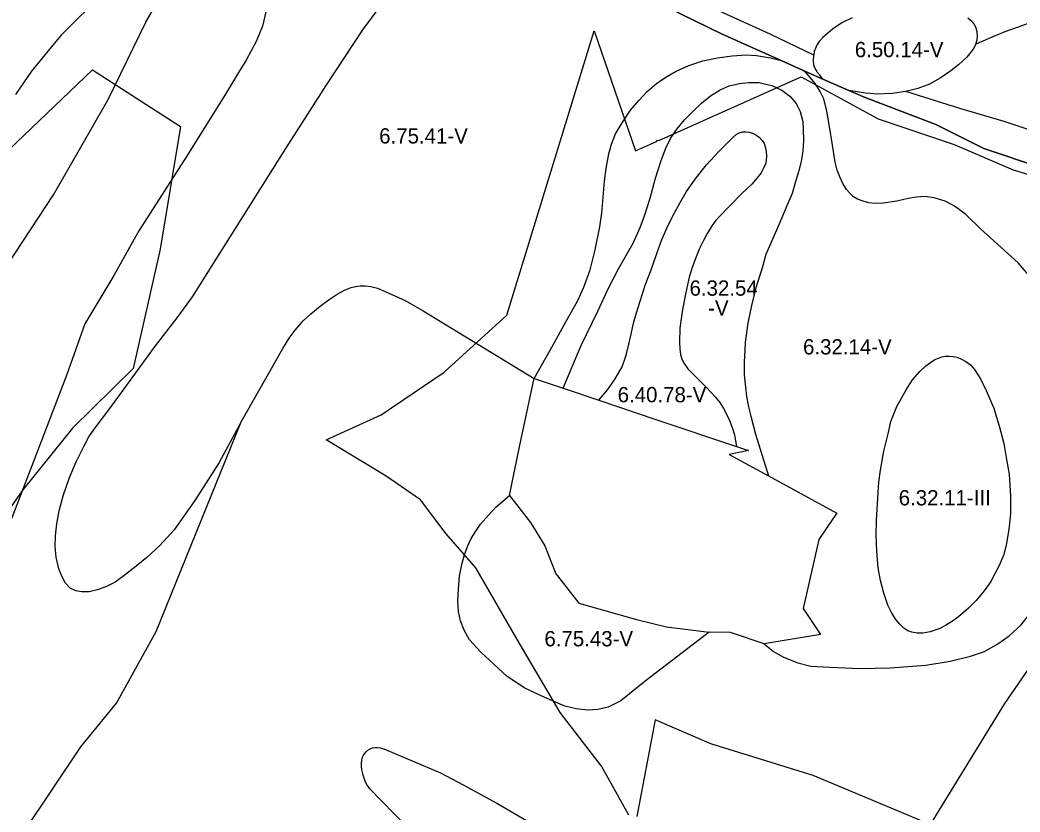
# Model space of a CAD drawing. Extents: x -555156 to -540209, y -1046851 to -1035695.
# Drawn here: x -543276 to -542621, y -1041348 to -1040830 of the extents above; entities that cross this region are included whole.
import ezdxf

# ---------------------------------------------------------------- set-up
doc = ezdxf.new("R2010")
doc.units = 0
for name, color, linetype in [('Vrstva 27', 7, 'Continuous'), ('Vrstva 28', 7, 'Continuous'), ('Vrstva 29', 7, 'Continuous')]:
    doc.layers.add(name, color=color, linetype=linetype)

msp = doc.modelspace()

# ---------------------------------------------------------------- linework, layer by layer
at = {"layer": 'Vrstva 28'}
for points in [[(-542750.36, -1040868.71), (-542763.73, -1040862.75), (-542777.64, -1040856.56), (-542816.73, -1040839.15), (-542851.59, -1040821.98), (-542893.18, -1040804.96), (-542959.22, -1040781.23), (-542988.31, -1040771.92)], [(-543114.91, -1040780.64), (-543113, -1040792.52), (-543112.57, -1040803.33), (-543112.79, -1040813.08), (-543114.48, -1040823.69), (-543117.02, -1040834.08), (-543121.05, -1040844.04), (-543127.62, -1040856.34), (-543132.71, -1040864.4), (-543140.55, -1040877.5), (-543166.14, -1040918.69), (-543197.89, -1040967.9), (-543214.21, -1040997.22), (-543233.03, -1041028.81), (-543244.9, -1041062.1), (-543267.79, -1041121.9), (-543281.99, -1041158.59)], [(-542959.22, -1040781.23), (-542909.59, -1040799.06), (-542893.18, -1040804.96), (-542851.59, -1040821.98), (-542816.73, -1040839.15), (-542777.68, -1040856.54)], [(-543293.87, -1041005.52), (-543253.63, -1040944.47), (-543217.93, -1040882.13), (-543193.27, -1040831.47), (-543168.15, -1040787.72)], [(-543168.15, -1040787.72), (-543177.6, -1040791.96), (-543189.11, -1040796.93), (-543197, -1040800.47), (-543210.35, -1040807.47), (-543220.95, -1040814.25), (-543229.21, -1040820.83), (-543239.6, -1040831.01), (-543248.92, -1040840.12), (-543257.19, -1040850.09), (-543268, -1040863.45), (-543278.38, -1040878.72)], [(-543130.8, -1041093.03), (-543145.27, -1041119.62), (-543161.13, -1041144.58), (-543174.7, -1041163.61), (-543184.14, -1041173.91), (-543192.53, -1041181.84), (-543198.49, -1041186.61), (-543207.55, -1041193.82), (-543213.23, -1041197.83), (-543219.04, -1041200.88), (-543224.92, -1041202.96), (-543230.32, -1041204.2), (-543235.1, -1041204.27), (-543239.11, -1041203.51), (-543242.71, -1041201.78), (-543245.74, -1041198.58), (-543248.28, -1041193.97), (-543250.22, -1041189.12), (-543251.79, -1041181.61), (-543252.52, -1041174.7), (-543252.28, -1041167.68), (-543251.55, -1041159.68), (-543249.97, -1041151.32), (-543247.35, -1041141.35), (-543243.11, -1041129.48), (-543238.75, -1041119.18), (-543233.66, -1041108.76), (-543230.51, -1041102.82), (-543227.12, -1041097.73), (-543216.74, -1041084.25), (-543207.31, -1041071.47), (-543187.6, -1041044.12), (-543172.13, -1041023.97), (-543162.8, -1041011.25), (-543101.67, -1040914.04), (-543075.39, -1040872.9), (-543051.23, -1040836.43), (-543033.64, -1040812.47)], [(-542756.44, -1040853.01), (-542785, -1040839.22), (-542848.26, -1040810.19), (-542852.98, -1040808.28)], [(-542731.25, -1040828.69), (-542737.56, -1040831.59), (-542741.32, -1040833.98), (-542744.05, -1040835.95), (-542747.21, -1040838.59), (-542750.37, -1040841.41), (-542752.76, -1040844.14), (-542754.19, -1040846.13), (-542755.12, -1040847.94), (-542756.1, -1040850.57), (-542756.44, -1040853.01)], [(-542650.35, -1040845.79), (-542649.58, -1040843.06), (-542649.33, -1040840.49), (-542649.58, -1040837.76), (-542650.27, -1040835.28), (-542651.29, -1040832.89), (-542653.08, -1040830.93), (-542655.56, -1040828.88)], [(-542615.09, -1040831.94), (-542622.74, -1040834.63), (-542630.36, -1040837.32), (-542637.68, -1040840.31), (-542650.35, -1040845.79)], [(-542650.35, -1040845.79), (-542652.15, -1040849.03), (-542656.18, -1040854.26), (-542661.7, -1040859.35), (-542666.63, -1040863.38), (-542673.8, -1040868.01), (-542680.67, -1040871.9), (-542688.29, -1040874.74), (-542696.06, -1040876.83)], [(-542939.35, -1041064.58), (-542926.79, -1041042.67), (-542918.53, -1041027.62), (-542910.9, -1041014.05), (-542906.87, -1041004.93), (-542902.63, -1040993.48), (-542899.45, -1040980.33), (-542896.27, -1040965.28), (-542895, -1040956.37), (-542894.15, -1040945.98), (-542893.31, -1040935.59), (-542892.25, -1040927.11), (-542890.37, -1040917.64), (-542888.67, -1040911.34), (-542886.01, -1040904.43), (-542881.77, -1040897.4), (-542876.32, -1040888.92), (-542870.87, -1040882.62), (-542865.3, -1040876.8), (-542859.25, -1040871.59), (-542853.07, -1040867.35), (-542846.41, -1040863.59), (-542838.05, -1040859.84), (-542828.85, -1040856.69), (-542819.4, -1040854.75), (-542809.83, -1040853.42), (-542800.51, -1040852.81), (-542793.73, -1040853.17)], [(-542793.73, -1040853.17), (-542784.64, -1040854.75), (-542777.68, -1040856.54)], [(-542777.68, -1040856.54), (-542763.73, -1040862.75)], [(-542752.24, -1040866.38), (-542754.15, -1040864.09), (-542754.66, -1040863.13), (-542755.46, -1040861.65), (-542756.29, -1040859.46), (-542756.63, -1040856.48), (-542756.44, -1040853.01)], [(-542605.19, -1041009.3), (-542622.63, -1040988.87), (-542647.58, -1040966.45), (-542656.91, -1040957.36), (-542664.29, -1040951.91), (-542670.35, -1040948.64), (-542677.62, -1040946.45), (-542683.43, -1040945.49), (-542689.12, -1040945.85), (-542694.7, -1040946.73), (-542702.1, -1040948.53), (-542710.89, -1040949.78), (-542715.73, -1040950.06), (-542720.3, -1040949.64), (-542724.11, -1040948.6), (-542727.84, -1040947.22), (-542730.34, -1040945.76), (-542732.83, -1040943.41), (-542734.9, -1040940.92), (-542737.33, -1040936.97), (-542739.33, -1040932.75), (-542740.99, -1040928.18), (-542742.33, -1040923.02), (-542744.14, -1040911.99), (-542746.2, -1040899.63), (-542747.9, -1040889.69), (-542749.76, -1040881.63), (-542752.12, -1040876.72), (-542755.51, -1040871.66), (-542758.55, -1040867.78), (-542761.46, -1040864.67), (-542763.73, -1040862.75)], [(-542763.73, -1040862.75), (-542750.36, -1040868.71)], [(-542920.34, -1041070.98), (-542908.65, -1041043.54), (-542897.63, -1041020.64), (-542891.06, -1041006.43), (-542884.06, -1040992.86), (-542874.53, -1040976.11), (-542869.86, -1040965.72), (-542867.09, -1040958.26), (-542863.49, -1040946.59), (-542859.89, -1040933.45), (-542856.29, -1040921.99), (-542853.11, -1040913.94), (-542850.14, -1040907.58), (-542845.99, -1040901.52), (-542840.91, -1040895.34), (-542835.58, -1040889.88), (-542829.76, -1040884.43), (-542823.95, -1040879.71), (-542817.53, -1040875.71), (-542811.72, -1040873.16), (-542804.94, -1040871.59), (-542798.88, -1040870.86), (-542792.34, -1040870.98)], [(-542792.34, -1040870.98), (-542783.74, -1040872.8), (-542777.32, -1040875.95), (-542772, -1040879.95), (-542767.88, -1040884.55), (-542765.33, -1040889.88), (-542763.64, -1040896.43), (-542763.28, -1040901.52), (-542763.03, -1040909.15), (-542763.52, -1040915.69), (-542764.61, -1040922.6), (-542766.3, -1040929.39), (-542768.48, -1040936.54), (-542770.6, -1040943.47), (-542773.99, -1040951.71), (-542779.2, -1040964.07), (-542787.68, -1040983.46), (-542790.25, -1040993.01), (-542794.28, -1041005.1), (-542797.03, -1041016.76), (-542799.58, -1041028.42), (-542801.27, -1041040.93), (-542801.44, -1041046.4), (-542801.8, -1041053.67), (-542801.8, -1041062.16), (-542801.08, -1041070.28), (-542800.35, -1041076.33), (-542799.14, -1041083.12), (-542797.57, -1041089.3), (-542794.42, -1041101.17), (-542786.05, -1041128.35)], [(-542750.36, -1040868.71), (-542752.24, -1040866.38)], [(-542750.36, -1040868.71), (-542733.5, -1040876.07), (-542722.73, -1040880.77), (-542676.59, -1040898.5), (-542645.13, -1040914.12), (-542608.12, -1040926.61), (-542540.62, -1040949.39), (-542505.86, -1040963.01), (-542488.41, -1040969.43), (-542470.89, -1040975.38), (-542466.21, -1040977.19), (-542458.71, -1040980.09)], [(-542733.5, -1040876.07), (-542750.36, -1040868.71)], [(-542458.71, -1040980.09), (-542470.89, -1040975.38), (-542488.41, -1040969.43), (-542505.86, -1040963.01), (-542540.62, -1040949.39), (-542608.12, -1040926.61), (-542645.13, -1040914.12), (-542676.59, -1040898.5), (-542722.73, -1040880.77), (-542733.5, -1040876.07)], [(-542719.43, -1040878.21), (-542722.65, -1040877.88), (-542733.5, -1040876.07)], [(-542696.06, -1040876.83), (-542705.02, -1040878.18)], [(-542458.71, -1040980.09), (-542467.28, -1040973.4), (-542476.18, -1040966.45), (-542485.66, -1040960.23), (-542490.57, -1040957.01), (-542497.82, -1040952.26), (-542517.16, -1040941.28), (-542543.3, -1040929.09), (-542581.99, -1040913.92), (-542608.91, -1040903.99), (-542631.91, -1040896.4), (-542660.93, -1040888.03), (-542696.06, -1040876.83)], [(-542705.02, -1040878.18), (-542715.33, -1040878.62), (-542719.43, -1040878.21)], [(-542896.85, -1041078.89), (-542891.1, -1041071.73), (-542886.22, -1041064.94), (-542881.77, -1041057.1), (-542879.02, -1041049.46), (-542877.23, -1041042.07), (-542875.78, -1041035.52), (-542874.33, -1041028.49), (-542872.39, -1041021.59), (-542869.84, -1041013.95), (-542866.57, -1041003.65), (-542862.7, -1040993.48), (-542859.07, -1040982.81), (-542855.8, -1040973.6), (-542852.28, -1040965.85), (-542848.53, -1040958.21), (-542843.81, -1040949.41), (-542839.69, -1040942.26), (-542833.27, -1040933.41), (-542826.61, -1040924.81), (-542818.49, -1040916.08), (-542809.41, -1040906.87), (-542807.08, -1040904.85), (-542805.28, -1040903.88), (-542802.85, -1040903.26), (-542800.71, -1040903.19), (-542798.63, -1040903.4)], [(-542798.63, -1040903.4), (-542796.35, -1040904.09), (-542794.2, -1040905.06), (-542791.92, -1040906.93), (-542790.12, -1040908.93), (-542788.81, -1040910.94), (-542787.91, -1040913.64), (-542787.49, -1040916.07), (-542787.28, -1040918.91), (-542787.56, -1040922.02), (-542788.04, -1040924.1), (-542789.15, -1040927.01), (-542790.81, -1040929.98), (-542793.37, -1040933.31), (-542796.83, -1040937.46), (-542803.55, -1040943.83), (-542818.49, -1040959), (-542820.41, -1040961.3), (-542822.98, -1040964.76), (-542826.02, -1040969.75), (-542828.51, -1040974.38), (-542831.28, -1040980.06), (-542834.05, -1040986.71), (-542835.66, -1040991.42), (-542837.81, -1040998.42), (-542839.95, -1041008.32), (-542842.31, -1041019.4), (-542843.41, -1041027.08), (-542844.04, -1041031.72), (-542844.17, -1041040.93), (-542844.04, -1041045.22), (-542843.57, -1041048.85), (-542842.6, -1041052.03), (-542841.15, -1041054.87), (-542838.73, -1041058.26), (-542834.16, -1041062.9), (-542826.55, -1041070.52), (-542820.87, -1041076.61), (-542817.76, -1041080.42), (-542815.34, -1041084.3), (-542813.38, -1041088.09), (-542811.44, -1041092.03), (-542809.78, -1041096.67), (-542808.26, -1041101.52), (-542807.56, -1041105.4), (-542806.89, -1041109.16)], [(-543130.8, -1041093.03), (-543119.35, -1041072.67), (-543103.67, -1041045.1), (-543099.43, -1041038.23), (-543095.55, -1041033.02), (-543090.35, -1041026.96), (-543085.38, -1041022.35), (-543079.2, -1041017.26), (-543073.27, -1041012.9), (-543068.06, -1041009.51), (-543062.86, -1041006.6), (-543058.86, -1041005.08), (-543056.02, -1041004.38), (-543053.05, -1041003.9), (-543049.79, -1041003.9), (-543046.13, -1041004.38)], [(-543046.13, -1041004.38), (-543041.77, -1041005.42), (-543036.64, -1041007.64), (-543023.7, -1041013.66), (-543011.94, -1041020.45), (-542939.35, -1041064.58)], [(-542665.31, -1041050.18), (-542662.5, -1041050.77), (-542659.73, -1041051.88), (-542656.85, -1041053.54), (-542653.96, -1041055.6), (-542651.17, -1041058.71), (-542647.29, -1041064.77), (-542643.54, -1041072.41), (-542638.57, -1041084.16), (-542634.95, -1041096.55), (-542632.16, -1041107.21), (-542630.35, -1041117.63), (-542628.65, -1041127.21), (-542627.8, -1041141.75), (-542627.68, -1041153.14), (-542628.77, -1041163.32), (-542630.22, -1041172.65), (-542632.04, -1041179.8), (-542635.1, -1041187.1), (-542640.64, -1041197.42), (-542644.86, -1041203.58), (-542650.19, -1041209.95), (-542655.17, -1041214.94), (-542661.67, -1041220.61), (-542665.62, -1041223.45), (-542670.19, -1041226.29), (-542673.99, -1041228.3), (-542680.22, -1041230.45), (-542685.13, -1041231.28), (-542688.73, -1041231.28), (-542692.19, -1041230.72), (-542694.82, -1041229.75), (-542697.45, -1041228.02), (-542700.15, -1041225.53), (-542702.71, -1041222.34), (-542705.36, -1041218.26), (-542707.9, -1041212.93), (-542710.57, -1041205.17), (-542712.75, -1041196.93), (-542714.2, -1041188.45), (-542715.05, -1041177.54), (-542715.53, -1041167.12), (-542715.41, -1041157.55), (-542714.2, -1041139.25), (-542713.73, -1041132.49), (-542712.76, -1041124.74), (-542710.46, -1041112.14), (-542707.79, -1041100.75), (-542705.88, -1041092.71), (-542702.01, -1041083.02), (-542695.91, -1041071.99), (-542691.72, -1041065.58), (-542687.01, -1041060.16), (-542683.11, -1041056.39), (-542680.1, -1041054.06), (-542677.13, -1041052.28), (-542674.88, -1041051.25), (-542672.59, -1041050.46), (-542670.37, -1041049.98)], [(-542670.37, -1041049.98), (-542667.76, -1041049.94), (-542665.31, -1041050.18)], [(-542955.45, -1041141.18), (-542948.74, -1041109.37), (-542939.89, -1041067.45), (-542939.35, -1041064.58)], [(-542939.35, -1041064.58), (-542920.34, -1041070.98)], [(-542920.34, -1041070.98), (-542896.85, -1041078.89)], [(-542896.85, -1041078.89), (-542859.72, -1041091.39), (-542806.89, -1041109.16)], [(-543367.43, -1041496.06), (-543358.52, -1041484.25), (-543291.66, -1041388.79), (-543235.84, -1041305.67), (-543212.48, -1041277.09), (-543186.52, -1041230.33), (-543130.8, -1041093.03)], [(-542806.89, -1041109.16), (-542798.99, -1041111.82), (-542811.78, -1041114.34), (-542786.05, -1041128.35)], [(-542786.05, -1041128.35), (-542741.2, -1041152.77), (-542743.82, -1041156.54), (-542753.11, -1041169.93), (-542763.35, -1041215.27), (-542751.91, -1041232.29), (-542788.89, -1041238.38)], [(-542824.82, -1041230.74), (-542866.71, -1041262.8), (-542882.57, -1041275.65), (-542890.93, -1041279.65), (-542897.71, -1041281.34), (-542904.25, -1041281.77), (-542911.76, -1041280.92), (-542919.15, -1041279.1), (-542932.35, -1041273.53), (-542945.31, -1041267.23), (-542956.93, -1041259.59), (-542974.13, -1041243.84), (-542981.46, -1041235.66), (-542985.09, -1041229.36), (-542987.51, -1041223.18), (-542988.84, -1041217.12), (-542989.21, -1041210.21), (-542988.84, -1041202.58), (-542988.12, -1041193.98), (-542986.54, -1041186.34), (-542984.73, -1041179.8), (-542982.55, -1041174.11), (-542980.37, -1041169.38), (-542977.46, -1041164.53), (-542974.43, -1041160.05), (-542969.1, -1041153.99), (-542964.14, -1041148.54), (-542955.45, -1041141.18)], [(-542955.45, -1041141.18), (-542941.68, -1041158.79)], [(-542941.68, -1041158.79), (-542932.33, -1041174.09), (-542924.99, -1041192.52), (-542924, -1041193.79), (-542910.14, -1041211.61), (-542872.43, -1041222.33), (-542852.79, -1041227.26), (-542824.82, -1041230.74)], [(-542788.89, -1041238.38), (-542782.63, -1041243.39), (-542776.22, -1041247.02), (-542766.89, -1041250.78), (-542758.29, -1041252.96), (-542745.79, -1041253.66), (-542726.08, -1041254.5), (-542706.37, -1041254.08), (-542683.05, -1041252.17), (-542667.16, -1041249.63), (-542653.81, -1041246.45), (-542644.69, -1041243.26), (-542636, -1041238.39), (-542628.59, -1041233.09), (-542620.74, -1041225.88), (-542615.37, -1041218.81), (-542605.62, -1041201.21)], [(-542788.89, -1041238.38), (-542810.78, -1041230.84), (-542824.82, -1041230.74)], [(-543022.78, -1041357.76), (-543046.73, -1041333.16), (-543047.7, -1041331.9), (-543048.81, -1041330.08), (-543049.72, -1041328.14), (-543050.47, -1041326.28), (-543051.14, -1041324.18), (-543051.62, -1041322.29), (-543051.93, -1041320.47), (-543052.13, -1041318.53), (-543052.21, -1041316.67), (-543052.05, -1041314.61), (-543051.66, -1041312.83), (-543051.14, -1041311.68), (-543050.31, -1041310.3), (-543049.24, -1041308.99), (-543048.1, -1041307.96), (-543046.51, -1041307.01), (-543045.01, -1041306.46), (-543043.43, -1041306.18)], [(-543043.43, -1041306.18), (-543041.89, -1041306.18), (-543040.07, -1041306.46)], [(-543040.07, -1041306.46), (-543037.66, -1041307.01), (-543000.54, -1041322.67), (-542985.71, -1041330.52), (-542963.67, -1041342.6), (-542941.62, -1041355.54)]]:
    msp.add_lwpolyline(points, dxfattribs=at)
at = {"layer": 'Vrstva 29'}
for points in [[(-542859.281638, -1040909.543894), (-542858.57, -1040908.57), (-542857.747526, -1040908.857424), (-542764.611991, -1040867.182004), (-542714.161992, -1040894.643997), (-542664.604006, -1040911.536003), (-542625.996009, -1040928.001997), (-542562.621009, -1040947.166002), (-542548.649, -1040889.425993), (-542527.839996, -1040825.278004), (-542510.349005, -1040758.724995), (-542490.184002, -1040695.784996), (-542472.397994, -1040635.904997), (-542454.404994, -1040581.157999), (-542445.100004, -1040533.381993)], [(-542877.440007, -1041350.445005), (-542895.164993, -1041318.373), (-542922.274005, -1041283.234991), (-542950.505009, -1041234.946993), (-542977.412996, -1041188.591993), (-542996.824, -1041166.252998), (-543013.604995, -1041143.996005), (-543036.141993, -1041128.581993), (-543075.238996, -1041104.698991), (-543039.230008, -1041088.516999), (-542998.020994, -1041060.594992), (-542957.188997, -1041023.203992), (-542899.936005, -1040837.117004), (-542872.960991, -1040915.665003), (-542859.281638, -1040909.543894)], [(-543297.815007, -1040929.155006), (-543228.173006, -1040862.656001), (-543170.672997, -1040899.772006), (-543183.919998, -1040980.084009), (-543201.555007, -1041058.190008), (-543241.266006, -1041097.217995), (-543273.686001, -1041137.452995), (-543299.047992, -1041173.264992)], [(-542345.88, -1041377.29), (-542367.660512, -1041344.508223), (-542394.932983, -1041336.838013), (-542454.263977, -1041318.11499), (-542518.365906, -1041305.021973), (-542553.908476, -1041280.808173), (-542554.76, -1041280.73), (-542555.053022, -1041280.028437), (-542567.642029, -1041271.452026), (-542575.473022, -1041231.346985), (-542594.271912, -1041223.169006), (-542631.637024, -1041277.340027), (-542680.179016, -1041356.603027), (-542756.71991, -1041324.510986), (-542823.747986, -1041303.672913), (-542860.137024, -1041287.958984), (-542872.159973, -1041351.276001)]]:
    msp.add_lwpolyline(points, dxfattribs=at)

# ---------------------------------------------------------------- texts
at = {"layer": 'Vrstva 27'}
for s, p in [('6.50.14-V', (-542729.540884, -1040854.34)), ('6.75.41-V', (-543040.631006, -1040910.85)), ('6.32.54', (-542837.643149, -1041010.45)), ('-V', (-542825.447104, -1041023.45)), ('6.32.14-V', (-542763.390288, -1041048.91)), ('6.40.78-V', (-542884.650459, -1041080.21)), ('6.32.11-III', (-542700.836548, -1041147.69)), ('6.75.43-V', (-542932.555522, -1041239.94))]:
    msp.add_text(s, height=10, dxfattribs=at).set_placement(p)

doc.saveas('drawing.dxf')
